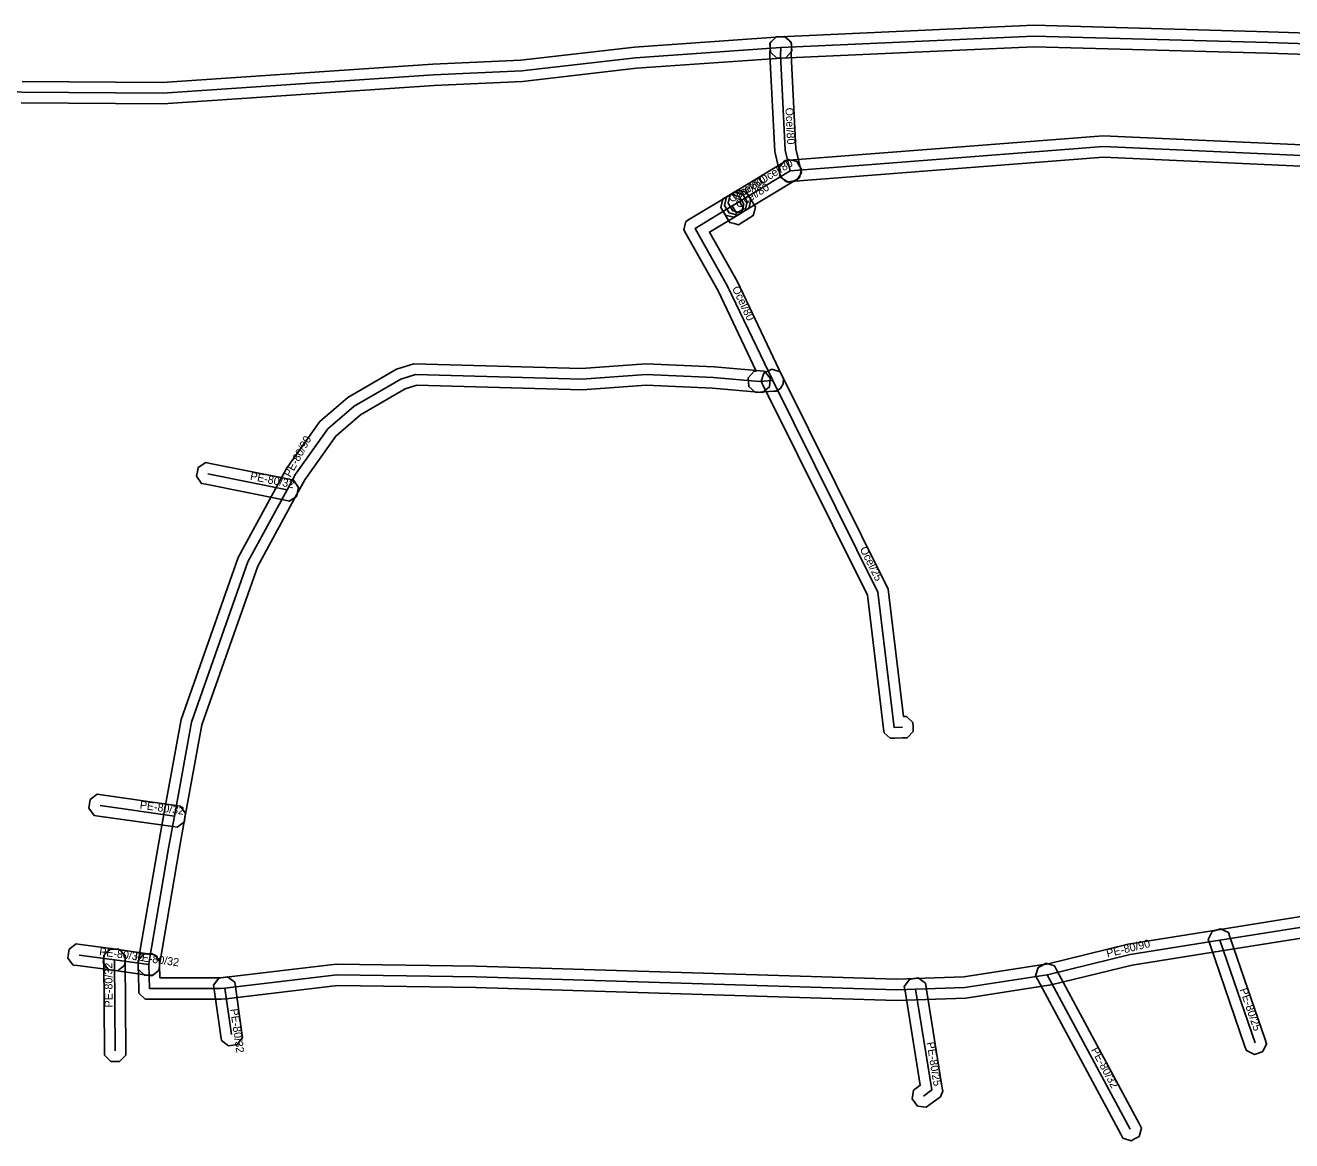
# Model space of a CAD drawing. Extents: x -569373 to -565022, y -1135090 to -1131496.
# Drawn here: x -565922.5 to -565803.8, y -1133879.2 to -1133774.6 of the extents above; entities that cross this region are included whole.
import ezdxf

# ---------------------------------------------------------------- set-up
doc = ezdxf.new("R2010")
doc.units = 0
for name, color, linetype in [('1', 7, 'Continuous'), ('24', 7, 'Continuous'), ('30', 7, 'Continuous')]:
    doc.layers.add(name, color=color, linetype=linetype)

msp = doc.modelspace()

# ---------------------------------------------------------------- linework, layer by layer
at = {"layer": '1'}
for points in [[(-565800.414, -1133777.459), (-565806.001, -1133777.27), (-565827.922, -1133776.651), (-565851.605, -1133777.719), (-565852.019, -1133777.738), (-565852.63, -1133777.179), (-565852.649, -1133776.765), (-565852.668, -1133776.351), (-565852.109, -1133775.74), (-565851.695, -1133775.721), (-565827.938, -1133774.649), (-565805.939, -1133775.27), (-565800.346, -1133775.461)], [(-565922.746, -1133779.91), (-565909.63, -1133780.02), (-565884.257, -1133778.292), (-565876.01, -1133777.913), (-565865.363, -1133776.684), (-565851.72, -1133775.722), (-565851.307, -1133775.693), (-565850.681, -1133776.237), (-565850.652, -1133776.65), (-565850.623, -1133777.063), (-565851.167, -1133777.689), (-565851.58, -1133777.718), (-565865.177, -1133778.676), (-565875.85, -1133779.907), (-565884.143, -1133780.288), (-565909.57, -1133782.02), (-565922.834, -1133781.91)], [(-565802.217, -1133787.868), (-565821.404, -1133787.012), (-565850.703, -1133789.287), (-565851.116, -1133789.319), (-565851.745, -1133788.78), (-565851.777, -1133788.367), (-565851.809, -1133787.954), (-565851.27, -1133787.325), (-565850.857, -1133787.293), (-565821.436, -1133785.008), (-565802.103, -1133785.872)], [(-565798.316, -1133859.468), (-565810.352, -1133861.388), (-565818.712, -1133862.721), (-565826.314, -1133864.579), (-565826.527, -1133864.617), (-565834.296, -1133865.807), (-565838.983, -1133865.979), (-565839.771, -1133866.009), (-565840.807, -1133866.051), (-565847.882, -1133865.809), (-565880.232, -1133864.82), (-565893.208, -1133864.641), (-565903.638, -1133865.873), (-565904.088, -1133865.93), (-565910.823, -1133865.91), (-565911.229, -1133865.909), (-565911.809, -1133865.342), (-565911.82, -1133864.937), (-565911.88, -1133862.707), (-565911.891, -1133862.293), (-565911.321, -1133861.691), (-565910.907, -1133861.68), (-565910.493, -1133861.669), (-565909.891, -1133862.239), (-565909.88, -1133862.653), (-565909.846, -1133863.913), (-565904.212, -1133863.93), (-565903.882, -1133863.887), (-565893.312, -1133862.639), (-565880.188, -1133862.82), (-565847.818, -1133863.811), (-565840.813, -1133864.049), (-565839.849, -1133864.011), (-565839.057, -1133863.981), (-565834.484, -1133863.813), (-565826.853, -1133862.643), (-565826.726, -1133862.621), (-565819.108, -1133860.759), (-565810.668, -1133859.412), (-565798.624, -1133857.492)]]:
    msp.add_lwpolyline(points, dxfattribs=at)
for points in [[(-565850.634, -1133776.348), (-565850.651, -1133776.762), (-565850.679, -1133777.426), (-565850.236, -1133786.211), (-565849.806, -1133788.064), (-565849.712, -1133788.467), (-565850.151, -1133789.17), (-565850.554, -1133789.264), (-565850.957, -1133789.358), (-565851.66, -1133788.919), (-565851.754, -1133788.516), (-565852.224, -1133786.489), (-565852.681, -1133777.434), (-565852.649, -1133776.678), (-565852.632, -1133776.264), (-565852.022, -1133775.704), (-565851.608, -1133775.721), (-565851.194, -1133775.738)], [(-565849.908, -1133788.93), (-565850.262, -1133789.145), (-565855.002, -1133792.015), (-565855.356, -1133792.23), (-565856.16, -1133792.032), (-565856.375, -1133791.678), (-565856.59, -1133791.324), (-565856.392, -1133790.52), (-565856.038, -1133790.305), (-565851.298, -1133787.435), (-565850.944, -1133787.22), (-565850.14, -1133787.418), (-565849.925, -1133787.772), (-565849.71, -1133788.126)], [(-565856.355, -1133790.498), (-565856.35, -1133790.499), (-565856.048, -1133790.311), (-565855.696, -1133790.092), (-565854.89, -1133790.28), (-565854.671, -1133790.632), (-565854.439, -1133791.005), (-565854.247, -1133791.317), (-565854.03, -1133791.671), (-565854.128, -1133792.075), (-565854.225, -1133792.478), (-565854.58, -1133792.694), (-565855.27, -1133793.114), (-565855.627, -1133793.331), (-565856.032, -1133793.23), (-565856.436, -1133793.13), (-565856.65, -1133792.771), (-565857.06, -1133792.081), (-565857.272, -1133791.725), (-565857.067, -1133790.922), (-565856.711, -1133790.71)], [(-565854.649, -1133791.802), (-565855.004, -1133792.016), (-565855.344, -1133792.221), (-565855.699, -1133792.435), (-565856.502, -1133792.236), (-565856.716, -1133791.881), (-565856.93, -1133791.526), (-565856.731, -1133790.723), (-565856.376, -1133790.509), (-565856.036, -1133790.304), (-565855.681, -1133790.09), (-565854.878, -1133790.289), (-565854.664, -1133790.644), (-565854.45, -1133790.999)], [(-565854.156, -1133807.058), (-565853.95, -1133807.045), (-565857.528, -1133799.541), (-565860.551, -1133794.171), (-565860.75, -1133793.818), (-565860.544, -1133793.035), (-565860.198, -1133792.825), (-565856.718, -1133790.715), (-565856.364, -1133790.5), (-565855.56, -1133790.697), (-565855.345, -1133791.052), (-565855.13, -1133791.406), (-565855.327, -1133792.21), (-565855.682, -1133792.425), (-565858.334, -1133794.033), (-565855.752, -1133798.619), (-565851.507, -1133807.52), (-565851.4, -1133807.745), (-565851.422, -1133808.242), (-565851.548, -1133808.457), (-565851.674, -1133808.672), (-565852.098, -1133808.933), (-565852.347, -1133808.948), (-565853.617, -1133809.028), (-565854.03, -1133809.054), (-565854.652, -1133808.506), (-565854.678, -1133808.093), (-565854.704, -1133807.68)], [(-565854.989, -1133792.007), (-565855.344, -1133792.221), (-565855.684, -1133792.426), (-565856.039, -1133792.64), (-565856.842, -1133792.441), (-565857.056, -1133792.086), (-565857.27, -1133791.731), (-565857.071, -1133790.928), (-565856.716, -1133790.714), (-565856.376, -1133790.509), (-565856.021, -1133790.295), (-565855.218, -1133790.494), (-565855.004, -1133790.849), (-565854.79, -1133791.204)], [(-565853.355, -1133809.062), (-565853.768, -1133809.026), (-565858.036, -1133808.648), (-565864.256, -1133808.372), (-565870.278, -1133808.811), (-565885.761, -1133808.374), (-565886.864, -1133808.721), (-565891.048, -1133811.158), (-565893.365, -1133813.148), (-565896.27, -1133817.25), (-565897.032, -1133818.649), (-565900.673, -1133825.328), (-565905.9, -1133840.207), (-565907.496, -1133848.93), (-565908.045, -1133851.934), (-565909.641, -1133861.27), (-565909.88, -1133862.665), (-565909.88, -1133862.68), (-565909.88, -1133863.094), (-565910.466, -1133863.68), (-565910.88, -1133863.68), (-565911.294, -1133863.68), (-565911.88, -1133863.094), (-565911.88, -1133862.68), (-565911.88, -1133862.495), (-565911.613, -1133860.932), (-565910.015, -1133851.586), (-565909.464, -1133848.57), (-565907.84, -1133839.693), (-565902.507, -1133824.512), (-565898.788, -1133817.691), (-565897.97, -1133816.19), (-565894.855, -1133811.792), (-565892.212, -1133809.522), (-565887.676, -1133806.879), (-565886.039, -1133806.366), (-565870.322, -1133806.809), (-565864.284, -1133806.368), (-565857.904, -1133806.652), (-565853.592, -1133807.034), (-565853.179, -1133807.07), (-565852.648, -1133807.705), (-565852.684, -1133808.118), (-565852.72, -1133808.531)], [(-565841.588, -1133827.479), (-565840.146, -1133839.426), (-565839.872, -1133839.419), (-565839.271, -1133839.99), (-565839.26, -1133840.404), (-565839.249, -1133840.818), (-565839.82, -1133841.419), (-565840.234, -1133841.43), (-565841.004, -1133841.45), (-565841.391, -1133841.46), (-565841.977, -1133840.954), (-565842.023, -1133840.57), (-565843.532, -1133828.061), (-565853.306, -1133808.395), (-565853.49, -1133808.024), (-565853.226, -1133807.239), (-565852.855, -1133807.054), (-565852.484, -1133806.87), (-565851.699, -1133807.134), (-565851.514, -1133807.505)], [(-565897.701, -1133819.232), (-565898.107, -1133819.15), (-565905.537, -1133817.66), (-565905.943, -1133817.579), (-565906.402, -1133816.889), (-565906.32, -1133816.483), (-565906.239, -1133816.077), (-565905.549, -1133815.618), (-565905.143, -1133815.7), (-565897.713, -1133817.19), (-565897.307, -1133817.271), (-565896.848, -1133817.961), (-565896.93, -1133818.367), (-565897.011, -1133818.773)], [(-565908.211, -1133849.798), (-565908.621, -1133849.74), (-565915.581, -1133848.75), (-565915.991, -1133848.692), (-565916.488, -1133848.029), (-565916.43, -1133847.619), (-565916.372, -1133847.209), (-565915.709, -1133846.712), (-565915.299, -1133846.77), (-565908.339, -1133847.76), (-565907.929, -1133847.818), (-565907.432, -1133848.481), (-565907.49, -1133848.891), (-565907.548, -1133849.301)], [(-565809.699, -1133859.683), (-565809.564, -1133860.075), (-565806.254, -1133869.695), (-565806.119, -1133870.086), (-565806.483, -1133870.831), (-565806.875, -1133870.966), (-565807.266, -1133871.101), (-565808.011, -1133870.737), (-565808.146, -1133870.345), (-565811.456, -1133860.725), (-565811.591, -1133860.334), (-565811.227, -1133859.589), (-565810.835, -1133859.454), (-565810.444, -1133859.319)], [(-565917.699, -1133860.734), (-565917.289, -1133860.789), (-565913.969, -1133861.229), (-565913.558, -1133861.283), (-565913.054, -1133861.941), (-565913.109, -1133862.351), (-565913.163, -1133862.762), (-565913.821, -1133863.266), (-565914.231, -1133863.211), (-565917.551, -1133862.771), (-565917.962, -1133862.717), (-565918.466, -1133862.059), (-565918.411, -1133861.649), (-565918.357, -1133861.238)], [(-565914.369, -1133861.172), (-565913.959, -1133861.23), (-565910.739, -1133861.69), (-565910.329, -1133861.748), (-565909.832, -1133862.411), (-565909.89, -1133862.821), (-565909.948, -1133863.231), (-565910.611, -1133863.728), (-565911.021, -1133863.67), (-565914.241, -1133863.21), (-565914.651, -1133863.152), (-565915.148, -1133862.489), (-565915.09, -1133862.079), (-565915.032, -1133861.669)], [(-565915.037, -1133871.171), (-565915.04, -1133870.757), (-565915.1, -1133862.227), (-565915.103, -1133861.813), (-565914.521, -1133861.223), (-565914.107, -1133861.22), (-565913.693, -1133861.217), (-565913.103, -1133861.799), (-565913.1, -1133862.213), (-565913.04, -1133870.743), (-565913.037, -1133871.157), (-565913.619, -1133871.747), (-565914.033, -1133871.75), (-565914.447, -1133871.753)], [(-565826.005, -1133862.791), (-565825.809, -1133863.156), (-565818.029, -1133877.626), (-565817.833, -1133877.991), (-565818.071, -1133878.785), (-565818.436, -1133878.981), (-565818.801, -1133879.177), (-565819.595, -1133878.939), (-565819.791, -1133878.574), (-565827.571, -1133864.104), (-565827.767, -1133863.739), (-565827.529, -1133862.945), (-565827.164, -1133862.749), (-565826.799, -1133862.553)], [(-565902.828, -1133864.329), (-565902.77, -1133864.739), (-565902.15, -1133869.089), (-565902.092, -1133869.499), (-565902.589, -1133870.162), (-565902.999, -1133870.22), (-565903.409, -1133870.278), (-565904.072, -1133869.781), (-565904.13, -1133869.371), (-565904.75, -1133865.021), (-565904.808, -1133864.611), (-565904.311, -1133863.948), (-565903.901, -1133863.89), (-565903.491, -1133863.832)], [(-565838.099, -1133864.412), (-565838.033, -1133864.821), (-565836.513, -1133874.261), (-565836.468, -1133874.537), (-565836.679, -1133875.055), (-565836.903, -1133875.222), (-565837.683, -1133875.802), (-565838.016, -1133876.049), (-565838.835, -1133875.929), (-565839.082, -1133875.597), (-565839.329, -1133875.264), (-565839.209, -1133874.445), (-565838.877, -1133874.198), (-565838.584, -1133873.98), (-565840.007, -1133865.139), (-565840.073, -1133864.73), (-565839.588, -1133864.059), (-565839.179, -1133863.993), (-565838.77, -1133863.927)]]:
    msp.add_lwpolyline(points, close=True, dxfattribs=at)
at = {"layer": '24'}
for points in [[(-565851.65, -1133776.72), (-565865.27, -1133777.68), (-565875.93, -1133778.91), (-565884.2, -1133779.29), (-565909.6, -1133781.02), (-565922.79, -1133780.91), (-565937.15, -1133779.75), (-565967.56, -1133777.19), (-565969.28, -1133790.6), (-565994.83, -1133786.35), (-566032.26, -1133779.25), (-566051.11, -1133775.65), (-566051.45, -1133775.6), (-566052.17, -1133775.47), (-566052.97, -1133775.3)], [(-565732.83, -1133781.01), (-565732.87, -1133781.33), (-565743.55, -1133779.28), (-565746.94, -1133778.83), (-565762.3, -1133776.81), (-565764.44, -1133776.86), (-565779.09, -1133777.19), (-565791.76, -1133776.76), (-565800.38, -1133776.46), (-565805.97, -1133776.27), (-565827.93, -1133775.65), (-565851.65, -1133776.72)], [(-565851.65, -1133776.72), (-565851.68, -1133777.43), (-565851.23, -1133786.35), (-565850.78, -1133788.29)], [(-565850.78, -1133788.29), (-565821.42, -1133786.01), (-565802.16, -1133786.87), (-565781.34, -1133788.3), (-565759.03, -1133789.81), (-565752.22, -1133790.23), (-565745.75, -1133790.62), (-565742.94, -1133790.48), (-565741.73, -1133790.42), (-565740.24, -1133791.16), (-565732.63, -1133791.74), (-565731.58, -1133791.82), (-565718.04, -1133792.97), (-565716.24, -1133793.2), (-565709.13, -1133795.77), (-565709.12, -1133796.59), (-565705.23, -1133798.32), (-565694.98, -1133802.4), (-565694.2, -1133802.71)], [(-565850.78, -1133788.29), (-565855.52, -1133791.16)], [(-565856.2, -1133791.57), (-565855.79, -1133792.26), (-565855.1, -1133791.84), (-565855.29, -1133791.53), (-565855.52, -1133791.16)], [(-565855.52, -1133791.16), (-565855.86, -1133791.365)], [(-565856.2, -1133791.57), (-565859.68, -1133793.68), (-565856.64, -1133799.08), (-565852.41, -1133807.95), (-565853.68, -1133808.03)], [(-565855.86, -1133791.365), (-565856.2, -1133791.57)], [(-565853.68, -1133808.03), (-565857.97, -1133807.65), (-565864.27, -1133807.37), (-565870.3, -1133807.81), (-565885.9, -1133807.37), (-565887.27, -1133807.8), (-565891.63, -1133810.34), (-565894.11, -1133812.47), (-565897.12, -1133816.72), (-565897.91, -1133818.17), (-565901.59, -1133824.92), (-565906.87, -1133839.95), (-565908.48, -1133848.75), (-565909.03, -1133851.76), (-565910.627, -1133861.101), (-565910.88, -1133862.58), (-565910.88, -1133862.68)], [(-565840.26, -1133840.43), (-565841.03, -1133840.45), (-565842.56, -1133827.77), (-565852.41, -1133807.95)], [(-565897.91, -1133818.17), (-565905.34, -1133816.68)], [(-565908.48, -1133848.75), (-565915.44, -1133847.76)], [(-565910.88, -1133862.68), (-565910.82, -1133864.91), (-565904.15, -1133864.93), (-565903.76, -1133864.88), (-565893.26, -1133863.64), (-565880.21, -1133863.82), (-565847.85, -1133864.81), (-565840.81, -1133865.05), (-565839.81, -1133865.01), (-565839.02, -1133864.98), (-565834.39, -1133864.81), (-565826.69, -1133863.63), (-565826.52, -1133863.6), (-565818.91, -1133861.74), (-565810.51, -1133860.4), (-565798.47, -1133858.48)], [(-565810.51, -1133860.4), (-565807.2, -1133870.02)], [(-565917.42, -1133861.78), (-565914.1, -1133862.22)], [(-565914.04, -1133870.75), (-565914.1, -1133862.22)], [(-565914.1, -1133862.22), (-565910.88, -1133862.68)], [(-565826.69, -1133863.63), (-565818.91, -1133878.1)], [(-565903.76, -1133864.88), (-565903.14, -1133869.23)], [(-565839.02, -1133864.98), (-565837.5, -1133874.42), (-565838.28, -1133875)]]:
    msp.add_lwpolyline(points, dxfattribs=at)

# ---------------------------------------------------------------- texts
at = {"layer": '30'}
for s, rotation, p in [('Ocel/80', 272.88803, (-565851.22, -1133782.38)), ('Ocel/80', 31.19429, (-565853.393, -1133789.551)), ('Ocel/80', 31.08751, (-565855.933, -1133791.088)), ('Ocel/80', 31.08751, (-565856.273, -1133791.293)), ('Ocel/80', 31.32869, (-565855.604, -1133791.825)), ('Ocel/80', 295.49593, (-565856.239, -1133799.301)), ('PE-80/90', 61.41723, (-565897.614, -1133817.059)), ('PE-80/32', 348.66041, (-565901.425, -1133817.225)), ('Ocel/25', 296.42612, (-565844.272, -1133823.724)), ('PE-80/32', 351.90448, (-565911.76, -1133848.055)), ('PE-80/32', 352.45058, (-565915.56, -1133861.8)), ('PE-80/90', 13.73469, (-565821.035, -1133862.011)), ('PE-80/32', 351.8699, (-565912.241, -1133862.257)), ('PE-80/32', 90.40301, (-565914.27, -1133866.685)), ('PE-80/25', 288.98705, (-565808.655, -1133865.01)), ('PE-80/32', 278.11166, (-565903.25, -1133866.855)), ('PE-80/25', 279.14708, (-565837.983, -1133869.98)), ('PE-80/32', 298.26533, (-565822.6, -1133870.665))]:
    msp.add_text(s, height=0.75, rotation=rotation, dxfattribs=at).set_placement(p)

doc.saveas('drawing.dxf')
